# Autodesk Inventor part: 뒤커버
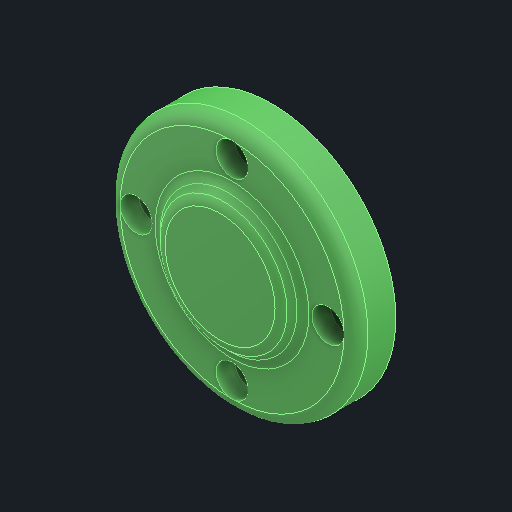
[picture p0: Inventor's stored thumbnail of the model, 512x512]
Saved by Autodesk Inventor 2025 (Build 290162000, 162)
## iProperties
Created: 2025-08
Part Number: 뒤커버
Material: 알루미늄 6061
Document SubType Name: Modeling
Designer: infra023
Density: 2.71 g/cm^3
Appearance: 기본값
Author: jhkim
Sending System: Autodesk Inventor 2026
Preprocessor: ST-DEVELOPER v20.1
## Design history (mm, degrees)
feature "솔리드1"
node "솔리드2"
